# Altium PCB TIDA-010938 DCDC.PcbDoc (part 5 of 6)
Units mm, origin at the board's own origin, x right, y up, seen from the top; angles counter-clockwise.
Board outline 280 x 174.95 mm, 4 copper layers (Top Layer, Layer 1, Layer 2, Bottom Layer), stack 1.787 mm thick; 409 components, 218 nets, 1371 pads, 2268 vias.
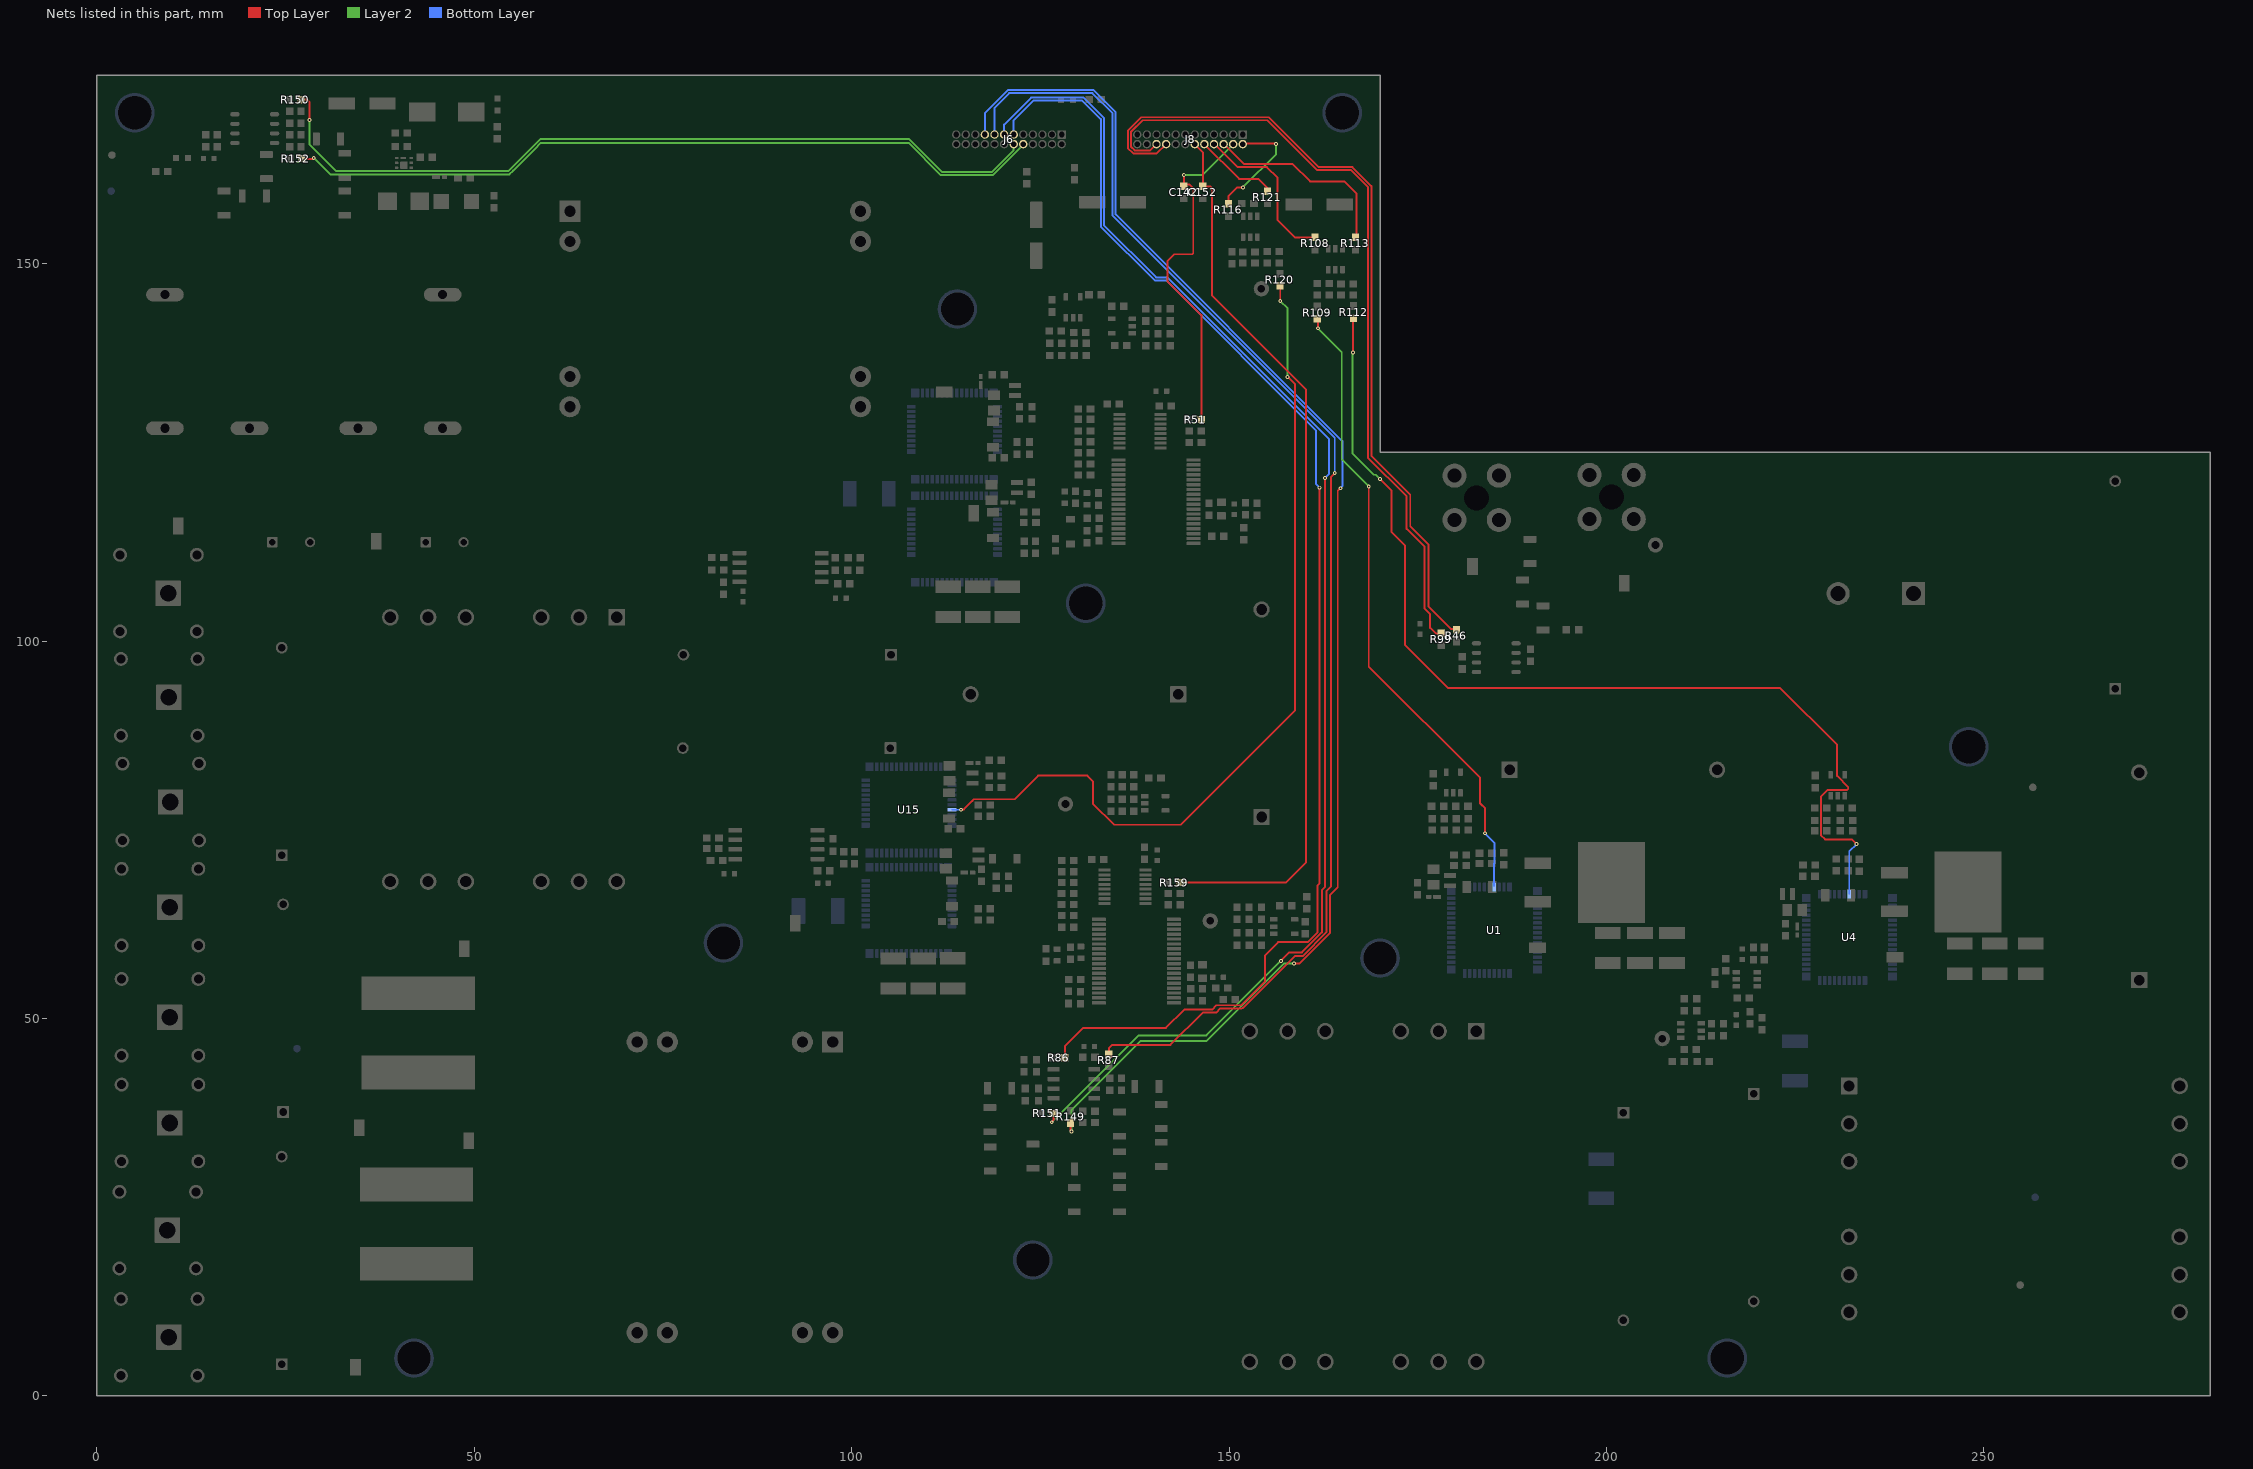
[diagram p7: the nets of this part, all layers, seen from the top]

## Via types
v1: diameter 0.508, hole 0.254, Top Layer to Bottom Layer, tented both sides, 1783 vias
v2: diameter 0.508, hole 0.254, Top Layer to Bottom Layer, 485 vias

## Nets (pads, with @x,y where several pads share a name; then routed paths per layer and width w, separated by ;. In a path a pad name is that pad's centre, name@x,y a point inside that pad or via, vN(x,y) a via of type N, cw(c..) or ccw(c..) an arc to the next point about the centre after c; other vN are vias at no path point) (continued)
TEMP_Bat_L2_init: R120.1 U15.49 | length 115.1
  Top Layer w0.254: v1(114.494,77.656) 114.543,77.704 114.869,77.704 115.978,78.813 115.978,78.858 116.163,79.044 121.58,79.044 124.699,82.163 131.233,82.163 131.966,81.43 131.966,78.466 134.766,75.667 143.594,75.667 158.75,90.824 158.75,134 v1(157.75,135) ; R120.1@156.733,147.072 156.778,147.027 v1(156.778,145.057)
  Layer 2 w0.254: v1(156.778,145.057) v1(156.778,145.057) 157.75,144.085 v1(157.75,135)
  Bottom Layer w0.254: U15.49@113.287,77.656 v1(114.494,77.656)
TEMP_Batt_H1_Buff: C142.2 J8.4 R51.1 | length 46.5
  Top Layer w0.254: C142.2@144,160.29 C142.2@144,160.5 ; v1(144,161.75) C142.2@144,160.5 ; R51.1@146.319,129.353 146.319,143.181 141.83,147.67 141.83,150.328 142.752,151.25 145.101,151.25 145.25,151.399 145.25,160 144.75,160.5 C142.2@144,160.5
  Layer 2 w0.254: v1(144,161.75) 146.444,161.75 J8.4@150.54,165.846
TEMP_Batt_H2_Buff: C152.2 J8.12 R159.1 | length 119.6
  Top Layer w0.254: R159.1@143.513,68.004 157.504,68.004 160.196,70.696 160.196,133.305 147.75,145.751 147.75,160 147.5,160.25 146.54,160.25 146.54,164.766 J8.12@145.46,165.846
TEMP_Batt_L1_Buff: J8.2 R116.2 | length 15.4
  Top Layer w0.254: R116.2@149.907,157.919 149.907,158.956 151.058,160.108 v1(151.825,160.108) ; J8.2@151.91,165.787 152.036,165.913 156.176,165.913 v1(156.218,165.87)
  Layer 2 w0.254: v1(151.825,160.108) 156.223,164.506 156.223,165.865 v1(156.218,165.87)
TEMP_Batt_L2_Buff: J8.10 R121.2 | length 11
  Top Layer w0.254: J8.10@146.73,165.846 151.329,161.247 153.893,161.247 R121.2@155.282,159.857
TEMP_Boost1_Buff: J8.8 R108.2 | length 21.8
  Top Layer w0.254: J8.8@148,165.846 148.086,165.846 151.144,162.789 155.014,162.789 156.432,161.371 156.432,155.766 158.716,153.483 R108.2@161.385,153.483
TEMP_Boost1_init: R109.1 U1.49 | length 85
  Top Layer w0.254: R109.1@161.684,142.73 161.765,142.649 v1(161.765,141.45) ; v1(168.5,120.5) 168.5,96.629 183.269,81.86 183.269,78.48 183.929,77.82 v1(183.929,74.533)
  Layer 2 w0.254: v1(161.765,141.45) 164.931,138.285 164.931,124.069 v1(168.5,120.5)
  Bottom Layer w0.254: v1(183.929,74.533) 183.929,74.488 185.182,73.234 185.182,70.567 185.126,70.51 U1.49@185.126,67.517
TEMP_Boost2_Buff: J8.6 R113.2 | length 26.3
  Top Layer w0.254: J8.6@149.241,165.961 152.01,163.193 158.435,163.193 160.728,160.9 165.246,160.9 166.9,159.246 166.9,153.637 R113.2@166.745,153.483
TEMP_Boost2_init: R112.1 U4.49 | length 137
  Top Layer w0.254: v1(166.423,138.219) R112.1@166.423,142.744 ; R112.1@166.49,142.798 R112.1@166.544,142.744 ; v1(169.997,121.468) 171.5,119.965 171.5,114.5 173.3,112.7 173.3,99.5 179,93.8 222.985,93.8 230.551,86.234 230.551,82.14 232.042,80.649 232.042,80.439 231.893,80.29 229.305,80.29 228.408,79.393 228.408,74.273 228.97,73.711 232.533,73.711 v1(233.144,73.1)
  Layer 2 w0.254: v1(166.423,138.219) 166.374,138.171 166.374,137.991 166.369,137.986 166.369,124.829 169.163,122.035 169.43,122.035 v1(169.997,121.468)
  Bottom Layer w0.254: U4.49@232.169,66.475 232.169,72.125 v1(233.144,73.1)
VS_Batt1+: J6.10 R152.2 | length 101.9
  Top Layer w0.254: R152.2@27.106,163.927 27.132,163.901 28.533,163.901 28.654,164.022 v1(28.723,164.022) v1@28.733,164.012
  Layer 2 w0.254: v1(28.723,164.022) 30.91,161.835 54.641,161.835 55.131,162.325 55.137,162.325 58,165.188 58,165.194 58.806,166 107.543,166 111.811,161.732 118.708,161.732 122.73,165.754 J6.10@122.73,165.846
VS_Batt1-: J6.12 R150.2 | length 107.2
  Top Layer w0.254: R150.2@27.058,171.735 27.853,171.735 28.142,171.446 v1(28.142,169.064)
  Layer 2 w0.254: v1(28.142,169.064) 28.142,165.811 31.662,162.291 54.526,162.291 54.964,162.729 54.969,162.729 57.596,165.356 57.596,165.361 58.735,166.5 107.614,166.5 111.978,162.136 118.541,162.136 121.459,165.054 121.459,165.845 J6.12@121.46,165.846
VS_Boost1+: J6.15 R87.2 | length 178.2
  Top Layer w0.254: R87.2@134.064,45.253 134.064,46.077 134.487,46.5 142.234,46.5 146.506,50.772 148.272,50.772 148.844,51.344 151.636,51.344 151.679,51.344 cw(c152.75,48.3) 151.848,51.398 158.7,58.25 159.727,58.25 162.9,61.423 162.9,66.886 163.514,67.5 163.514,121.764 v1(164,122.25)
  Bottom Layer w0.254: J6.15@118.92,167.116 118.92,170.663 120.852,172.595 131.883,172.595 134.566,169.912 134.566,156.363 164,126.929 v1(164,122.25)
VS_Boost1-: J6.17 R149.2 | length 192.5
  Top Layer w0.254: R149.2@129.004,36.147 129.004,35.175 129.11,35.069 v1(129.11,35) ; v1(158.6,57.3) 159.348,57.3 163.382,61.334 163.382,66.382 164.4,67.4 164.4,119.9 v1(164.75,120.25)
  Layer 2 w0.254: v1(129.11,35) 129.11,37.86 138.25,47 147,47 157.3,57.3 v1(158.6,57.3)
  Bottom Layer w0.254: J6.17@117.65,167.116 117.65,169.965 120.684,172.999 132.05,172.999 134.97,170.079 134.97,156.53 165,126.5 165,120.526 164.75,120.276 v1(164.75,120.25)
VS_Boost2+: J6.11 R86.2 | length 179.1
  Top Layer w0.254: R86.2@128.254,44.793 128.254,46.324 130.681,48.75 141.638,48.75 144.064,51.176 147.748,51.176 148.319,51.748 151.602,51.748 154.739,54.886 154.739,58.339 156.505,60.105 160.426,60.105 161.704,61.383 161.704,67.604 162,67.9 v1(162,120.325)
  Bottom Layer w0.254: J6.11@121.46,167.615 121.46,169.004 124.067,171.611 130.547,171.611 133.005,169.154 133.005,154.924 140.152,147.777 141.652,147.777 161.538,127.891 161.538,120.787 v1(162,120.325)
VS_Boost2-: J6.13 R151.2 | length 186
  Top Layer w0.254: v1(126.5,36.25) 126.5,36.316 126.75,36.566 126.75,37.205 R151.2@126.785,37.241 ; v1(156.875,57.625) 157.999,58.75 159.65,58.75 162.3,61.4 162.3,67 162.7,67.4 v1(162.7,121.6)
  Layer 2 w0.254: v1(126.5,36.25) 138,47.75 147,47.75 v1(156.875,57.625)
  Bottom Layer w0.254: J6.13@120.19,167.116 120.19,168.44 123.765,172.015 130.73,172.015 133.409,169.337 133.409,155.091 140.319,148.181 141.819,148.181 163.25,126.75 163.25,122.15 v1(162.7,121.6)
VS_DCDC_VDC+: J8.18 R46.2 | length 108.8
  Top Layer w0.254: J8.18@141.65,165.846 140.409,164.605 137.326,164.605 136.599,165.332 136.599,167.63 138.377,169.408 155.248,169.408 161.848,162.808 166.335,162.808 168.857,160.286 168.857,124.527 174,119.384 174,115.2 176.4,112.8 176.4,104.6 179.418,101.582 180.043,101.582 R46.2@180.125,101.5
VS_DCDC_VDC-: J8.20 R99.2 | length 105.2
  Top Layer w0.254: J8.20@140.38,165.846 139.543,165.009 137.493,165.009 137.003,165.499 137.003,167.463 138.544,169.004 155.081,169.004 161.681,162.404 166.167,162.404 168.384,160.188 168.384,124.316 173.531,119.169 173.531,114.873 175.9,112.504 175.9,104.3 176.64,103.56 176.64,101.76 177.38,101.02 R99.2@178.116,101.02
pads on no net: FID1.1 FID2.1 FID3.1 FID4.1 FID5.1 FID6.1 J1. J2.2 J2.3 J2.4 J2.5 J3.2 J3.3 J3.4 J3.5 J4. J5.2 J5.3 J5.4 J5.5 J6.18 J6.19 J6.20 J6.21 J7.2 J7.3 J7.4 J7.5 J8.22 J9.2 J9.3 J9.4 J9.5 J10.2 J10.3 J10.4 J10.5 J11.2 J11.3 J11.4 J11.5 J12.2 J12.3 J12.4 J12.5 L1.7 L1.8 L1.9 L1.10 L1.11 L1.12 L4.7 L4.8 L4.9 L4.10 L4.11 L4.12 L18.5 L18.6 L18.7 L18.8 LBL1.0 MP1. MP1.1 MP2. MP2.1 MP3. MP3.1 MP4. MP4.1 MP5. MP5.1 MP6. MP6.1 MP7. MP7.1 MP8. MP8.1 MP9. MP9.1 MP11. MP11.1 U1.1 U1.16 U1.17 U1.26 U1.43 U1.47 U1.52 U4.1 U4.16 U4.17 U4.26 U4.43 U4.47 U4.52 U6.32 U7.1 U7.16 U7.17 U7.26 U7.43 U7.47 U7.52 U9.7 U9.10 U10.1 U10.16 U10.17 U10.26 U10.43 U10.47 U10.52 U11.32 U12.1 U12.16 U12.17 U12.26 U12.43 U12.47 U12.52 U14.7 U14.10 U15.1 U15.16 U15.17 U15.26 U15.43 U15.47 U15.52 U23.1 U23.5 U23.8 U26.1 U26.5 U26.8

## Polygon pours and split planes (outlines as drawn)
"PV2 Bus-" on Top Layer "TOP_LAYER_PV2_BUS-_P402" (solid, pour order 402): 128.52,23.25 132.5,19.27 132.5,4.875 134.125,3.25 137.5,3.25 137.5,5.376 134.25,5.376 134.25,19.413 130.413,23.25
"PV2 Bus-" on Top Layer "TOP_LAYER_PV2_BUS-_P395" (solid, pour order 395): 128.5,24.822 130.279,24.822 130.346,24.889 130.5,24.736 130.5,23.217 128.5,23.217
"PV2 Bus+" on Top Layer "Top Layer-PV2 Bus+" (solid, pour order 383): 21 vertices, not listed, extent 32.75,0.75 119.485,30.25
"BAT Bus-" on Top Layer "TOP_LAYER_BAT_BUS-_P426" (solid, pour order 426): 5.361,83.9 12.1,83.9 12.1,61 5.361,61
Boost2_IN+ on Top Layer "TOP_LAYER_BOOST2_IN+_P206" (solid, pour order 206): 19 vertices, not listed, extent 0.825,14.95 50.959,35.985
"PV2 Bus-" on Top Layer "TOP_LAYER_PV2_BUS-_P435" (solid, pour order 435): 2.467,11.207 21.249,11.207 26.331,6.125 32.551,6.125 32.551,1.722 32.25,1.421 32.171,1.5 16.6,1.5 13.2,4.9 2.467,4.9
SW1 on Top Layer "TOP_LAYER_SW1_P425" (solid, pour order 425): 115.5,118.1 117.21,118.1 117.5,117.81 117.5,115.919 117.281,115.7 115.582,115.7 115.347,115.935 115.347,118
12V_HVN on Top Layer "TOP_LAYER_12V_HVN_P240" (solid, remove dead copper, pour order 240): 162.972,156.963 162.301,157.634 162.301,157.701 162.301,158.44 163.661,159.799 165.243,159.799 166.496,158.546 166.496,156.963
DC_Bus- on Top Layer "TOP_LAYER_DC_BUS-_P164" (solid, remove dead copper, pour order 164): 139.831,125.736 139.782,125.687 139.782,125.3 140.242,124.84 144.042,124.84 144.31,124.572 144.31,117.432 149.599,117.432 149.599,118.677 151.247,120.325 151.247,124.736 150.724,125.25 143.343,125.25 142.858,125.736
NetC2_2 on Top Layer "TOP_LAYER_NETC2_2_P314" (solid, pour order 314): 17,130 23,130 27,126 27,118 29,116 29,112 27,112 27,114 17,124
DC_Bus- on Top Layer "TOP_LAYER_DC_BUS-_P227" (solid, pour order 227): 27 vertices, not listed, extent 21,70 122.403,130
"BAT Bus+" on Top Layer "TOP_LAYER_BAT_BUS+_P195" (solid, pour order 195): 1,130 13,130 13,123 21,115 22.978,115 23.995,113.983 23.995,111.995 16,104 16,89 1,89
DC_Bus+ on Top Layer "TOP_LAYER_DC_BUS+_P179" (solid, remove dead copper, pour order 179): 197.406,80.5 189.047,72.141 189.047,71.12 190.291,69.877 193.873,69.877 196.25,67.5 196.25,61.114 197.241,60.123 212.323,60.123 216.75,64.55 216.75,76.5 212.75,80.5
NetD3_2 on Top Layer "Top Layer-NetD3_2" (solid, pour order 318): 20 vertices, not listed, extent 228.815,27.823 251.4,65.364
"PV2 Bus+" on Top Layer "TOP_LAYER_PV2_BUS+_P403" (solid, pour order 403): 218.817,11.48 219.941,11.48 224.42,7 252,7 252,24.25 228.25,24.25 222.25,18.25 217,18.25 217,13.297
DC_Bus+ on Top Layer "TOP_LAYER_DC_BUS+_P412" (solid, pour order 412): 17 vertices, not listed, extent 210,44.103 279.25,124
DC_Bus- on Top Layer "TOP_LAYER_DC_BUS-_P415" (solid, pour order 415): 110.378,135 110.378,132.303 110.681,132 113.903,132 114.153,132.25 114.153,135
"BAT Bus-" on Top Layer "TOP_LAYER_BAT_BUS-_P410" (solid, pour order 410): 36.002,114.654 36.169,114.821 38.75,114.821 38.75,111.654 36.002,111.654
"PV1 Bus-" on Top Layer "TOP_LAYER_PV1_BUS-_P408" (solid, pour order 408): 35.75,37.459 35.75,33.5 32.75,33.5 32.75,37.459
"PV2 Bus-" on Top Layer "TOP_LAYER_PV2_BUS-_P407" (solid, pour order 407): 32.25,6.125 32.852,6.727 34.413,6.727 34.981,6.159 34.981,1.421 32.25,1.421
Boost1_IN+ on Top Layer "TOP_LAYER_BOOST1_IN+_P205" (solid, pour order 205): 20 vertices, not listed, extent 1.664,43.45 51.462,66.367
DC_Bus+ on Top Layer "TOP_LAYER_DC_BUS+_P372" (solid, pour order 372): 181,111.25 181,108.5 181.5,108 183,108 183.625,108.625 183.625,111.5 186.5,111.5 188,113 190.75,113 190.75,114.25 181,114.25 180.25,113.5 180.25,112
DC_Bus+ on Top Layer "TOP_LAYER_DC_BUS+_P360" (solid, remove dead copper, pour order 360): 118.5,57.25 118.5,48.75 120.45,48.75 121.25,49.55 121.25,60.25 102.75,60.25 102.75,57.25
DC_Bus+ on Top Layer "TOP_LAYER_DC_BUS+_P086" (solid, remove dead copper, pour order 86): 117.5,110.957 119.157,109.3 124.048,109.3 124.048,105.869 110.241,105.869 109.083,107.027 109.083,109.736 110.272,110.925 114.86,110.957 116.775,110.957
"PV1 Bus+" on Top Layer "TOP_LAYER_PV1_BUS+_P398" (solid, pour order 398): 134.25,24.957 134.317,25.024 136.75,25.024 136.75,23.653 136.532,23.435 134.25,23.435
"PV1 Bus-" on Top Layer "TOP_LAYER_PV1_BUS-_P396" (solid, pour order 396): 140.133,30.833 142,30.833 142,26.818 140.133,26.818
NetR30_2 on Top Layer "TOP_LAYER_NETR30_2_P397" (solid, pour order 397): 117.197,42 119.04,42 119.04,37.5 117.197,37.5
NetR94_2 on Top Layer "TOP_LAYER_NETR94_2_P394" (solid, pour order 394): 140.067,35.935 140.133,36 142,36 142,33 140,33
NetR98_2 on Top Layer "TOP_LAYER_NETR98_2_P393" (solid, pour order 393): 141.75,42 141.75,38.25 140,38.25 140,42
NetR101_2 on Top Layer "TOP_LAYER_NETR101_2_P391" (solid, pour order 391): 130.179,31 130.346,30.833 130.346,27.25 128.674,27.25 128.674,31
NetR102_2 on Top Layer "TOP_LAYER_NETR102_2_P389" (solid, pour order 389): 126.75,31 126.75,29.281 126.781,29.25 123.137,29.25 123.137,31
NetR33_2 on Top Layer "TOP_LAYER_NETR33_2_P388" (solid, pour order 388): 134.25,30.068 136.75,30.068 136.75,26.818 134.25,26.818
NetR28_2 on Top Layer "TOP_LAYER_NETR28_2_P091" (solid, remove dead copper, pour order 91): 117.307,35.5 117.307,32.5 119.306,32.5 119.306,35.5
"PV1 Bus+" on Top Layer "TOP_LAYER_PV1_BUS+_P375" (solid, pour order 375): 17 vertices, not listed, extent 151,1.6 209.282,51.251
NetD1_2 on Top Layer "Top Layer-NetD1_2" (solid, pour order 320): 17 vertices, not listed, extent 170.75,44.727 193.227,66.717
DC_Bus- on Top Layer "TOP_LAYER_DC_BUS-_P029" (solid, remove dead copper, pour order 29): 100.9,51.25 100.9,55.073 107.473,55.073 116.481,55.073 116.481,51.25
NetR36_2 on Top Layer "TOP_LAYER_NETR36_2_P373" (solid, pour order 373): 134.25,35 136.75,35 136.75,31.812 134.25,31.812
NetL13_1 on Top Layer "TOP_LAYER_NETL13_1_P358" (solid, remove dead copper, pour order 358): 90,50 90,65 91,66 94,66 94,63 96,61 96,50 99,50 99,45 70,45 70,50
SW1 on Top Layer "TOP_LAYER_SW1_P121" (solid, remove dead copper, pour order 121): 136.045,125.753 136.045,125.641 136.304,125.397 136.304,118.995 135.804,118.495 134.304,118.495 134.304,119.167 127.749,119.167 127.749,120.038 128.71,120.999 132.555,120.999 133.936,122.38 133.936,124.282 134.633,124.979 134.633,125.753
"BAT Bus+" on Top Layer "TOP_LAYER_BAT_BUS+_P115" (solid, remove dead copper, pour order 115): 15.458,156.765 15.458,154.5 17.825,154.5 17.825,156.765
DC_Bus- on Top Layer "TOP_LAYER_DC_BUS-_P364" (solid, pour order 364): 135.5,159 135.75,159.25 139.25,159.25 139.75,158.75 139.75,157.25 139.5,157 135.75,157 135.5,157.25
DC_Bus- on Top Layer "TOP_LAYER_DC_BUS-_P363" (solid, pour order 363): 30,172 30.5,172.5 34.25,172.5 34.25,170.25 30.25,170.25 30,170.5
DC_Bus- on Top Layer "TOP_LAYER_DC_BUS-_P362" (solid, pour order 362): 40.5,170.75 41.25,171.5 44.75,171.5 44.75,168.75 41,168.75 40.5,169.25
NetL9_5 on Top Layer "TOP_LAYER_NETL9_5_P354" (solid, remove dead copper, pour order 354): 99.5,158.5 99.5,129.5 104,129.5 104,158.5
SW1 on Top Layer "TOP_LAYER_SW1_P122" (solid, remove dead copper, pour order 122): 136.289,115.935 133.789,115.935 133.789,117.135 134.389,117.135 134.489,117.035 136.289,117.035
DC_Bus- on Top Layer "TOP_LAYER_DC_BUS-_P182" (solid, remove dead copper, pour order 182): 210.5,58 210.5,55.43 209.944,54.874 198.103,54.874 197.143,55.834 197.143,57.435 197.708,58
DC_Bus- on Top Layer "TOP_LAYER_DC_BUS-_P181" (solid, remove dead copper, pour order 181): 258.569,56.862 259.073,56.214 259.073,54.402 257.726,53.055 245.972,53.055 244.172,54.855 244.172,56.055 244.979,56.862
DC_Bus+ on Top Layer "TOP_LAYER_DC_BUS+_P180" (solid, remove dead copper, pour order 180): 236.385,71.113 236.385,69.082 236.772,68.696 241.213,68.696 243.447,66.461 243.447,59.761 244.146,59.063 260.542,59.063 262,60.521 262,74.534 258.671,77.863 243.136,77.863
BatIN+ on Top Layer "TOP_LAYER_BATIN+_P219" (solid, pour order 219): 60,158 64,158 64,130 60,130
NetR21_2 on Top Layer "TOP_LAYER_NETR21_2_P238" (solid, pour order 238): 187.696,109.775 188.858,110.938 191.019,110.938 191.019,107.647 187.696,107.647
"PV1 Bus+" on Top Layer "TOP_LAYER_PV1_BUS+_P284" (solid, remove dead copper, pour order 284): 32.929,46.376 51.462,46.376 51.462,38.622 32.929,38.622
DC_Bus- on Top Layer "TOP_LAYER_DC_BUS-_P274" (solid, pour order 274): 17 vertices, not listed, extent 194.925,105.75 206.492,124.392
NetR26_2 on Top Layer "TOP_LAYER_NETR26_2_P239" (solid, pour order 239): 187.804,105.468 192.228,105.468 192.787,104.909 192.787,104 188.38,104 187.804,104.576
SW2 on Top Layer "TOP_LAYER_SW2_P123" (solid, remove dead copper, pour order 123): 19 vertices, not listed, extent 125.069,58.321 134.181,65.466
DC_Bus- on Top Layer "TOP_LAYER_DC_BUS-_P189" (solid, remove dead copper, pour order 189): 126.159,150.102 125.359,149.302 123.323,149.302 122.637,149.988 122.637,152.252 123.211,152.826 125.471,152.826 126.159,152.138
12V_HVN on Top Layer "TOP_LAYER_12V_HVN_P188" (solid, remove dead copper, pour order 188): 125.649,155.047 125.275,154.673 123.21,154.673 122.525,155.358 122.525,157.596 123.842,158.913 124.643,158.913 125.649,157.906
DC_Bus- on Top Layer "TOP_LAYER_DC_BUS-_P168" (solid, remove dead copper, pour order 168): 161.207,159.401 161.129,159.323 161.129,156.745 160.852,156.468 156.685,156.468 156.685,158.012 158.04,159.368 161.129,159.368
DC_Bus- on Top Layer "TOP_LAYER_DC_BUS-_P165" (solid, remove dead copper, pour order 165): 149.041,64.259 149.985,63.332 149.985,59.535 148.235,57.785 148.235,56.535 141.75,56.535 141.75,63.674 139.914,63.674 138.323,65.265 138.373,65.315 139.932,65.315 141.013,64.233 141.039,64.259
NetR69_2 on Top Layer "TOP_LAYER_NETR69_2_P136" (solid, remove dead copper, pour order 136): 31.809,167.407 31.809,164.382 32.038,164.153 33.7,164.153 33.7,165.028 33.736,165.064 32.696,166.104 32.696,167.407
NetR68_2 on Top Layer "TOP_LAYER_NETR68_2_P135" (solid, remove dead copper, pour order 135): 31.95,161.92 31.95,159.155 33.7,159.155 33.7,161.92
NetR44_2 on Top Layer "TOP_LAYER_NETR44_2_P134" (solid, remove dead copper, pour order 134): 21.567,161.691 21.592,161.666 21.592,160.353 21.791,160.154 21.791,158.117 22.818,158.117 23.317,158.616 23.317,160.908 23.317,161.691
NetR43_2 on Top Layer "TOP_LAYER_NETR43_2_P133" (solid, remove dead copper, pour order 133): 16.201,160.192 15.961,159.952 15.961,158.992 18.036,158.992 18.763,158.266 18.763,158.117 19.805,158.117 19.805,160.192
SW2 on Top Layer "TOP_LAYER_SW2_P124" (solid, remove dead copper, pour order 124): 133.623,55.11 131.087,55.11 131.087,56.31 131.687,56.31 131.787,56.21 133.623,56.21
"BAT Bus-" on Top Layer "TOP_LAYER_BAT_BUS-_P116" (solid, remove dead copper, pour order 116): 31.804,156.939 31.804,155.135 31.793,155.124 33.793,155.124 33.793,156.825 33.679,156.939
SW1 on Layer 1 "LAYER_1_SW1_P357" (solid, remove dead copper, pour order 357): 25 vertices, not listed, extent 95,105 136.175,132
DC_Bus- on Layer 1 "Layer 1-DC_Bus-" (solid, pour order 401): 99 vertices, not listed, extent 6.008,27.425 234.224,174.866
DC_Bus+ on Layer 1 "LAYER_1_DC_BUS+_P025" (solid, remove dead copper, pour order 25): 37 vertices, not listed, extent 92,48.801 144.759,110.99
"PV2 Bus+" on Layer 1 "LAYER_1_PV2_BUS+_P429" (solid, pour order 429): 229.724,24.3 229.724,6.8 252,6.8 252,24.3
NetD3_2 on Layer 1 "LAYER_1_NETD3_2_P428" (solid, pour order 428): 229.493,44 249.675,44 251.8,41.875 251.8,28.154 229.954,28.154 229.493,28.615
Boost1_IN+ on Layer 1 "LAYER_1_BOOST1_IN+_P427" (solid, pour order 427): 4.9,54.3 4.9,46.8 16.5,46.8 19.2,49.5 51.3,49.5 51.3,59.5 33.4,59.5 30.3,62.6 30.3,63.7 27.7,66.3 21.8,66.3 20.2,64.7 20.2,54.3
NetC2_2 on Layer 1 "LAYER_1_NETC2_2_P353" (solid, remove dead copper, pour order 353): 17,130 17,124 27,114 27,112 30,112 30,115 24,121 24,130
"BAT Bus-" on Layer 1 "LAYER_1_BAT_BUS-_P348" (solid, remove dead copper, pour order 348): 18 vertices, not listed, extent 5,59 41,130
"BAT Bus+" on Layer 1 "LAYER_1_BAT_BUS+_P347" (solid, remove dead copper, pour order 347): 1,89 15,89 15,130 1,130
DC_Bus- on Layer 1 "LAYER_1_DC_BUS-_P229" (solid, pour order 229): 18 vertices, not listed, extent 23,70 74.838,130
NetL13_1 on Layer 1 "LAYER_1_NETL13_1_P421" (solid, remove dead copper, pour order 421): 90,55 90,65 91,66 94,66 94,63 96,61 96,53 99,50 99,45 70,45 70,50 85,50
"PV1 Bus-" on Layer 1 "LAYER_1_PV1_BUS-_P261" (solid, pour order 261): 21 vertices, not listed, extent 1.225,19 201.526,42.2
DC_Bus- on Layer 1 "LAYER_1_DC_BUS-_P418" (solid, remove dead copper, pour order 418): 197.056,50.812 197.056,56.744 210.683,56.744 210.683,54.521 203,46.838 203,32 194,32 190,36 190,43.756
DC_Bus- on Layer 1 "LAYER_1_DC_BUS-_P417" (solid, remove dead copper, pour order 417): 222.811,47.429 222.811,60.023 227.209,64.421 229,64.421 229,58.5 230,57.5 233.82,57.5 233.82,51.717 229.532,47.429
DC_Bus- on Layer 1 "LAYER_1_DC_BUS-_P273" (solid, pour order 273): 19 vertices, not listed, extent 194.925,44.25 279.25,124.392
"PV2 Bus-" on Layer 1 "Layer 1-Boost2_IN-" (solid, pour order 309): 19 vertices, not listed, extent 0.825,0.95 227.525,42.75
DC_Bus+ on Layer 1 "LAYER_1_DC_BUS+_P054" (solid, remove dead copper, pour order 54): 188.5,86.5 185.769,86.5 185.769,81.266 188.5,78.536 188.5,70.572 189.124,69.948 193.72,69.948 196.25,67.418 196.25,61 197.056,60.194 206.186,60.194 207.831,61.839 207.831,86.5
SW2 on Layer 1 "LAYER_1_SW2_P359" (solid, remove dead copper, pour order 359): 94.75,76.282 94.75,67.673 99.591,67.673 99.591,73.409 96.718,76.282
NetC2_2 on Layer 1 "Layer 1-NetC2_2" (solid, pour order 291): 35,62 67.304,62 71.172,65.868 71.172,70.514 69.626,72.059 52.521,72.059 46.63,77.95 32.352,77.95 30,75.398 30,67
DC_Bus- on Layer 1 "LAYER_1_DC_BUS-_P345" (solid, remove dead copper, pour order 345): 210.683,58 210.683,55.25 209.861,54.428 198.549,54.428 197.056,55.922 197.056,57.251 197.804,58
DC_Bus- on Layer 1 "LAYER_1_DC_BUS-_P043" (solid, remove dead copper, pour order 43): 260.875,56.7 261.254,56.214 261.254,55.071 259.671,53.489 245.954,53.489 244.154,55.289 244.154,56.489 244.366,56.7
DC_Bus+ on Layer 1 "LAYER_1_DC_BUS+_P051" (solid, remove dead copper, pour order 51): 236.385,71.113 236.385,69.082 236.772,68.696 241.213,68.696 243.447,66.461 243.447,59.761 243.87,59.338 260.817,59.338 261.377,59.898 261.377,75.157 258.671,77.863 243.136,77.863
SW2 on Layer 1 "LAYER_1_SW2_P171" (solid, remove dead copper, pour order 171): 20 vertices, not listed, extent 111.137,51.59 134.976,74.272
"PV1 Bus-" on Bottom Layer "BOTTOM_LAYER_PV1_BUS-_P202" (solid, remove dead copper, pour order 202): 196.967,23.333 192.3,28 192.3,30 193.2,30.9 193.768,30.9 198.139,26.53 198.146,26.537 200.417,26.537 201.195,25.76 201.195,24.065 200.463,23.333
DC_Bus+ on Bottom Layer "BOTTOM_LAYER_DC_BUS+_P120" (solid, remove dead copper, pour order 120): 107.293,109.82 107.647,109.467 108.175,109.467 108.528,109.82 118.446,109.82 118.799,109.467 119.763,109.467 120.117,109.82 123.273,109.82 123.981,109.113 123.981,105.71 106.631,105.71 106.631,109.312 107.14,109.82
DC_Bus- on Bottom Layer "BOTTOM_LAYER_DC_BUS-_P046" (solid, remove dead copper, pour order 46): 223.311,47.75 223.311,46.243 226.633,46.243 226.934,46.544 226.934,47.75 229.95,47.75 233.8,51.6 233.8,64.55 232.795,65.686 228.884,65.686 227.15,64.029 225.744,64.029 223.311,61.596
DC_Bus+ on Bottom Layer "Bottom Layer-DC_Bus+" (solid, pour order 322): 55 vertices, not listed, extent 129.835,44.25 279,124.392
"PV2 Bus-" on Bottom Layer "BOTTOM_LAYER_PV2_BUS-_P434" (solid, pour order 434): 1.866,11.2 17.074,11.2 21.174,7.1 34.5,7.1 35.015,6.585 35.015,1.615 34.4,1 17.219,1 14.119,4.1 1.866,4.1
Boost2_IN+ on Bottom Layer "BOTTOM_LAYER_BOOST2_IN+_P433" (solid, pour order 433): 0.7,26.8 2.5,28.6 19.2,28.6 19.2,31.2 20.7,32.7 31,32.7 31.6,32.1 45.7,32.1 50.3,27.5 50.3,24.853 48.647,23.2 30.2,23.2 22.1,15.1 1.2,15.1 0.7,15.6
"PV1 Bus-" on Bottom Layer "BOTTOM_LAYER_PV1_BUS-_P432" (solid, pour order 432): 4.1,39.9 14.6,39.9 16.8,42.1 26.9,42.1 31.6,37.4 31.6,35.7 30.8,34.9 17.3,34.9 15,32.6 4.1,32.6
Boost1_IN+ on Bottom Layer "BOTTOM_LAYER_BOOST1_IN+_P431" (solid, pour order 431): 17 vertices, not listed, extent 4.1,46.7 48.1,66.6
SW1 on Bottom Layer "BOTTOM_LAYER_SW1_P430" (solid, pour order 430): 18 vertices, not listed, extent 121.247,111.156 135.95,132.108
DC_Bus- on Bottom Layer "Bottom Layer-DC_Bus-" (solid, pour order 406): 57 vertices, not listed, extent 6,68 175.5,174.554
NetC2_2 on Bottom Layer "BOTTOM_LAYER_NETC2_2_P352" (solid, remove dead copper, pour order 352): 17,130 29,130 29,112 26,112 26,116 17,125
"BAT Bus+" on Bottom Layer "BOTTOM_LAYER_BAT_BUS+_P351" (solid, remove dead copper, pour order 351): 5,89 12,89 12,130 5,130
DC_Bus- on Bottom Layer "BOTTOM_LAYER_DC_BUS-_P349" (solid, remove dead copper, pour order 349): 43,130 43,120 47,116 47,111 51,111 51,130
"BAT Bus-" on Bottom Layer "Bottom Layer-BAT Bus-" (solid, pour order 301): 21 vertices, not listed, extent 2.474,59.67 45.518,130
NetD3_2 on Bottom Layer "Bottom Layer-NetD3_2" (solid, pour order 324): 21 vertices, not listed, extent 229.5,27.823 251.6,65.354
DC_Bus+ on Bottom Layer "BOTTOM_LAYER_DC_BUS+_P027" (solid, remove dead copper, pour order 27): 120.45,48.75 121.2,49.5 121.25,49.5 121.25,60.25 102.628,60.25 102.628,55.324 117.75,55.324 117.75,48.75
"PV2 Bus+" on Bottom Layer "Bottom Layer-PV2 Bus+" (solid, pour order 368): 28 vertices, not listed, extent 32.75,2.752 252,30
"PV1 Bus+" on Bottom Layer "BOTTOM_LAYER_PV1_BUS+_P003" (solid, remove dead copper, pour order 3): 19 vertices, not listed, extent 32.803,21.324 166.5,51.5
NetD1_2 on Bottom Layer "Bottom Layer-NetD1_2" (solid, pour order 326): 23 vertices, not listed, extent 170.75,44.727 197.55,66.717
SW1 on Bottom Layer "Bottom Layer-SW1" (solid, pour order 381): 26 vertices, not listed, extent 95,104.925 118.5,122.5
BatIN+ on Bottom Layer "Bottom Layer-BatIN+" (solid, pour order 283): 17 vertices, not listed, extent 46.825,50.825 78.5,159.5
NetL13_1 on Bottom Layer "Bottom Layer-NetL13_1" (solid, pour order 213): 69.954,44.854 99,44.854 99,50.14 96.19,52.95 96.206,52.966 96.206,60.794 94,63 94,66 91.504,66 90.129,64.626 90.129,61.5 90.129,54.975 84.655,49.5 69.954,49.5
DC_Bus- on Bottom Layer "BOTTOM_LAYER_DC_BUS-_P061" (solid, remove dead copper, pour order 61): 106,134 109,137 119.416,137 123.056,133.36 123.056,132.069 123.065,132.069 123.502,131.612 123.502,126.852 122.105,125.617 107.383,125.617 106,127
DC_Bus- on Bottom Layer "Bottom_Layer-Bat_IN-" (solid, remove dead copper, pour order 163): 17 vertices, not listed, extent 88.1,76.118 126.5,103.658
SW2 on Bottom Layer "gan1_sw" (solid, remove dead copper, pour order 118): 18 vertices, not listed, extent 94.5,62.388 112.337,76.483
NetL9_5 on Bottom Layer "Bottom Layer-NetL9_5" (solid, pour order 333): 97.89,117.571 98.239,117.222 100.603,117.222 101.262,117.881 101.262,121.654 104,124.391 104,158.907 97.914,158.907 97.914,124.035 97.89,124.035
"PV2 Bus-" on Bottom Layer "BOTTOM_LAYER_PV2_BUS-_P069" (solid, remove dead copper, pour order 69): 222.8,41.318 222.8,37.978 220.422,35.6 220.422,27.478 227.5,27.478 227.5,41.059 226.934,41.626 226.633,41.927 223.409,41.927
DC_Bus- on Bottom Layer "BOTTOM_LAYER_DC_BUS-_P045" (solid, remove dead copper, pour order 45): 186.816,56.604 186.762,56.55 186.816,56.496 186.816,54.3 178.61,54.3 177.173,55.737 177.173,64.373 177.692,64.892 180.079,64.892 180.486,65.299 181.97,66.717 185.167,66.717 186.816,64.853
DC_Bus- on Bottom Layer "BOTTOM_LAYER_DC_BUS-_P272" (solid, pour order 272): 194.925,124.025 195.2,124.3 205.725,124.3 206.492,123.533 206.492,115.415 204.006,112.929 204.006,110.479 203.318,109.791 197.634,109.791 196.847,110.578 196.847,112.125 194.925,114.047
DC_Bus- on Bottom Layer "BOTTOM_LAYER_DC_BUS-_P201" (solid, remove dead copper, pour order 201): 197.399,33.095 195.356,35.138 195.356,38.156 196,38.8 198.5,38.8 200.145,37.155 200.145,34.077 200.395,33.827 201.119,33.102 201.119,31.294 200.924,31.099 197.7,31.099 197.399,31.399
SW2 on Bottom Layer "BOTTOM_LAYER_SW2_P015" (solid, remove dead copper, pour order 15): 124.116,53.143 125.669,51.59 132.906,51.59 133.912,52.595 133.912,64.06 134.737,64.885 134.726,64.895 134.726,69.94 134.726,71.172 131.598,74.272 124.116,74.272 116.326,74.272 116.326,62.559 123.037,62.559 124.116,61.327
DC_Bus- on Bottom Layer "BOTTOM_LAYER_DC_BUS-_P125" (solid, remove dead copper, pour order 125): 148.992,64.344 149.937,63.417 149.937,59.62 148.187,57.87 148.187,56.62 142.687,56.62 142.687,63.577 142.504,63.759 139.865,63.759 138.275,65.35 138.324,65.4 139.883,65.4 140.964,64.318 140.99,64.344
DC_Bus- on Layer 2 "Layer 2-DC_Bus-" (solid, pour order 377): 90 vertices, not listed, extent 87.4,32.25 278.75,137
NetD3_2 on Layer 2 "LAYER_2_NETD3_2_P440" (solid, pour order 440): 229,44 249.569,44 251.776,41.793 251.776,28.276 251.2,27.7 229.9,27.7 228.9,28.7
"PV2 Bus-" on Layer 2 "LAYER_2_PV2_BUS-_P439" (solid, pour order 439): 3.2,10.7 18.15,10.7 21.42,7.43 34.15,7.43 35.4,6.18 35.4,1.6 16.707,1.6 13.507,4.8 3.2,4.835
"PV1 Bus-" on Layer 2 "LAYER_2_PV1_BUS-_P438" (solid, pour order 438): 2.6,38.4 2.6,33.227 2.51,33.137 2.61,33.037 14.777,33.037 17.641,35.9 25.5,35.9 26.6,37 26.6,40.1 26,40.7 18,40.7 15.7,38.4 2.8,38.4
DC_Bus- on Layer 2 "LAYER_2_DC_BUS-_P404" (solid, pour order 404): 41 vertices, not listed, extent 6.132,108.176 177.5,174.5
BatIN+ on Layer 2 "Layer 2-BatIN+" (solid, pour order 281): 32 vertices, not listed, extent 46.825,1.95 102.825,158.95
"BAT Bus-" on Layer 2 "LAYER_2_BAT_BUS-_P437" (solid, pour order 437): 5.404,83.921 12.143,83.921 12.143,61.021 5.404,61.021
DC_Bus- on Layer 2 "LAYER_2_DC_BUS-_P350" (solid, remove dead copper, pour order 350): 43,130 43,120 47,116 47,111 51,111 51,130
NetC2_2 on Layer 2 "LAYER_2_NETC2_2_P197" (solid, pour order 197): 17,130 28,130 28,125 35.855,117.145 35.855,88.726 51.38,73.2 66.959,73.2 70.223,69.936 70.223,65.813 67.31,62.9 36.699,62.9 17,82.599
"BAT Bus+" on Layer 2 "LAYER_2_BAT_BUS+_P196" (solid, pour order 196): 15.458,156.939 18.349,156.939 18.349,136.35 15,133.001 15,89 1,89 1,130 7,130 15.458,138.458
"BAT Bus-" on Layer 2 "LAYER_2_BAT_BUS-_P117" (solid, remove dead copper, pour order 117): 33.843,129.95 33.9,130.007 38.861,130.007 38.861,129.964 39.875,128.95 39.875,126.964 38.861,125.95 32.849,125.95 32.849,125.956 31.854,126.95 31.854,137.703 31.854,156.506 33.729,156.506 33.843,156.393
"PV2 Bus+" on Layer 2 "LAYER_2_PV2_BUS+_P423" (solid, pour order 423): 217.841,24.3 252,24.3 252,7.1 251.776,6.876 219.161,6.876 212.1,13.937 212.1,22.48 213.92,24.3
NetL13_1 on Layer 2 "LAYER_2_NETL13_1_P419" (solid, remove dead copper, pour order 419): 90,55 90,65 91,66 94,66 94,63 96,61 96,53 99,50 99,45 70,45 70,50 85,50
"PV1 Bus+" on Layer 2 "LAYER_2_PV1_BUS+_P416" (solid, pour order 416): 185.1,8 191.3,1.8 207.05,1.8 209.25,4 209.25,15.077 205.75,18.577 205.75,18.701 173.549,18.701 165,27.25 165,51 154.25,51 149,45.75 149,14.25 155.25,8
Boost2_IN+ on Layer 2 "LAYER_2_BOOST2_IN+_P411" (solid, pour order 411): 17 vertices, not listed, extent 0.802,14.987 49,36.022
SW1 on Layer 2 "LAYER_2_SW1_P356" (solid, remove dead copper, pour order 356): 95,105 100.5,105 102,106.5 102,109.5 102.117,109.617 102.117,112.42 101.537,113 95,113
Boost1_IN+ on Layer 2 "LAYER_2_BOOST1_IN+_P304" (solid, pour order 304): 19 vertices, not listed, extent 1.664,43.45 47.178,66.367
no net on Bottom Solder "BOTTOM_LAYER_NONET_P106" (solid): 216.25,79.75 216.25,61.385 196,61.385 196,79.75
no net on Bottom Solder "BOTTOM_LAYER_NONET_P106" (solid): 263.5,78.5 263.5,60.135 243.25,60.135 243.25,78.5
no net on Top Solder "NONET_L-01_P-001" (solid): 253.75,72 253.75,62.5 261.75,62.5 261.75,72
no net on Top Solder "NONET_L-01_P-001" (solid): 207.5,73.25 207.5,63.75 215.5,63.75 215.5,73.25

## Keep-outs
Top Layer:
  region: 101.103,173.956 62.666,173.956 62.666,161.813 67.398,157.081 67.398,131.157 62.666,126.425 62.666,113.811 101.103,113.811 101.103,125.897 97.173,129.827 97.173,158.173 101.103,162.103
  region: 114.595,8.588 114.595,47.025 102.452,47.025 97.72,42.293 71.796,42.293 67.064,47.025 54.45,47.025 54.45,8.588 67.927,8.588 71.856,12.517 96.1,12.517 100.029,8.588
Keep-Out Layer:
  lines w0.5: 0,0 280,0 280,124.95 170,124.95 170,174.95 0,174.95 0,0

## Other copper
Top Layer:
  pour cut-out: 123.75,11.024 cw(c123.75,18.024) 116.75,18.024 cw(c123.75,18.024) 123.75,25.024 cw(c123.75,18.024) 130.75,18.024 cw(c123.75,18.024)
  pour cut-out: 24.637,34.656 cw(c24.637,37.656) 21.637,37.656 cw(c24.637,37.656) 24.637,40.656 cw(c24.637,37.656) 27.637,37.656 cw(c24.637,37.656)
  pour cut-out: 169.981,51 cw(c169.981,58) 162.981,58 cw(c169.981,58) 169.981,65 cw(c169.981,58) 176.981,58 cw(c169.981,58)
  pour cut-out: 82.981,53.274 cw(c82.981,60.274) 75.981,60.274 cw(c82.981,60.274) 82.981,67.274 cw(c82.981,60.274) 89.981,60.274 cw(c82.981,60.274)
  pour cut-out: 41.981,-1.976 cw(c41.981,5.024) 34.981,5.024 cw(c41.981,5.024) 41.981,12.024 cw(c41.981,5.024) 48.981,5.024 cw(c41.981,5.024)
  pour cut-out: 113.981,137.024 cw(c113.981,144.024) 106.981,144.024 cw(c113.981,144.024) 113.981,151.024 cw(c113.981,144.024) 120.981,144.024 cw(c113.981,144.024)
  pour cut-out: 247.981,79.024 cw(c247.981,86.024) 240.981,86.024 cw(c247.981,86.024) 247.981,93.024 cw(c247.981,86.024) 254.981,86.024 cw(c247.981,86.024)
  pour cut-out: 24.452,96.181 cw(c24.452,99.181) 21.452,99.181 cw(c24.452,99.181) 24.452,102.181 cw(c24.452,99.181) 27.452,99.181 cw(c24.452,99.181)
  pour cut-out: 48.849,100.19 cw(c48.849,103.19) 45.849,103.19 cw(c48.849,103.19) 48.849,106.19 cw(c48.849,103.19) 51.849,103.19 cw(c48.849,103.19)
  pour cut-out: 275.93,8.103 cw(c275.93,11.103) 272.93,11.103 cw(c275.93,11.103) 275.93,14.103 cw(c275.93,11.103) 278.93,11.103 cw(c275.93,11.103)
  pour cut-out: 275.93,13.103 cw(c275.93,16.103) 272.93,16.103 cw(c275.93,16.103) 275.93,19.103 cw(c275.93,16.103) 278.93,16.103 cw(c275.93,16.103)
  pour cut-out: 275.93,18.103 cw(c275.93,21.103) 272.93,21.103 cw(c275.93,21.103) 275.93,24.103 cw(c275.93,21.103) 278.93,21.103 cw(c275.93,21.103)
  pour cut-out: 275.93,28.103 cw(c275.93,31.103) 272.93,31.103 cw(c275.93,31.103) 275.93,34.103 cw(c275.93,31.103) 278.93,31.103 cw(c275.93,31.103)
  pour cut-out: 275.93,33.103 cw(c275.93,36.103) 272.93,36.103 cw(c275.93,36.103) 275.93,39.103 cw(c275.93,36.103) 278.93,36.103 cw(c275.93,36.103)
  pour cut-out: 275.93,38.103 cw(c275.93,41.103) 272.93,41.103 cw(c275.93,41.103) 275.93,44.103 cw(c275.93,41.103) 278.93,41.103 cw(c275.93,41.103)
  pour cut-out: 43.554,110.154 cw(c43.554,113.154) 40.554,113.154 cw(c43.554,113.154) 43.554,116.154 cw(c43.554,113.154) 46.554,113.154 cw(c43.554,113.154)
  pour cut-out: 43.849,100.19 cw(c43.849,103.19) 40.849,103.19 cw(c43.849,103.19) 43.849,106.19 cw(c43.849,103.19) 46.849,103.19 cw(c43.849,103.19)
  pour cut-out: 38.849,100.19 cw(c38.849,103.19) 35.849,103.19 cw(c38.849,103.19) 38.849,106.19 cw(c38.849,103.19) 41.849,103.19 cw(c38.849,103.19)
  pour cut-out: 68.849,65.19 cw(c68.849,68.19) 65.849,68.19 cw(c68.849,68.19) 68.849,71.19 cw(c68.849,68.19) 71.849,68.19 cw(c68.849,68.19)
  pour cut-out: 63.849,65.19 cw(c63.849,68.19) 60.849,68.19 cw(c63.849,68.19) 63.849,71.19 cw(c63.849,68.19) 66.849,68.19 cw(c63.849,68.19)
  pour cut-out: 58.849,65.19 cw(c58.849,68.19) 55.849,68.19 cw(c58.849,68.19) 58.849,71.19 cw(c58.849,68.19) 61.849,68.19 cw(c58.849,68.19)
  pour cut-out: 48.849,65.19 cw(c48.849,68.19) 45.849,68.19 cw(c48.849,68.19) 48.849,71.19 cw(c48.849,68.19) 51.849,68.19 cw(c48.849,68.19)
  pour cut-out: 43.849,65.19 cw(c43.849,68.19) 40.849,68.19 cw(c43.849,68.19) 43.849,71.19 cw(c43.849,68.19) 46.849,68.19 cw(c43.849,68.19)
  pour cut-out: 38.849,65.19 cw(c38.849,68.19) 35.849,68.19 cw(c38.849,68.19) 38.849,71.19 cw(c38.849,68.19) 41.849,68.19 cw(c38.849,68.19)
  pour cut-out: 4.981,163.024 cw(c4.981,170.024) -2.019,170.024 cw(c4.981,170.024) 4.981,177.024 cw(c4.981,170.024) 11.981,170.024 cw(c4.981,170.024)
  pour cut-out: 130.981,98.024 cw(c130.981,105.024) 123.981,105.024 cw(c130.981,105.024) 130.981,112.024 cw(c130.981,105.024) 137.981,105.024 cw(c130.981,105.024)
  pour cut-out: 215.981,-1.976 cw(c215.981,5.024) 208.981,5.024 cw(c215.981,5.024) 215.981,12.024 cw(c215.981,5.024) 222.981,5.024 cw(c215.981,5.024)
  pour cut-out: 164.981,163.024 cw(c164.981,170.024) 157.981,170.024 cw(c164.981,170.024) 164.981,177.024 cw(c164.981,170.024) 171.981,170.024 cw(c164.981,170.024)
  pour cut-out: 263.649,97.25 270.878,97.25 270.878,90 263.672,90
  pour cut-out: 68.25,11.725 68.25,5 100.75,5 100.75,11.725
  pour cut-out: 148.75,7.923 148.75,1 187.5,1 187.5,7.923
  pour cut-out: 237.149,110 244.378,110 244.378,102.75 237.172,102.75
  text ".Layer_Name" at -2.675,-151.856 h1.52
